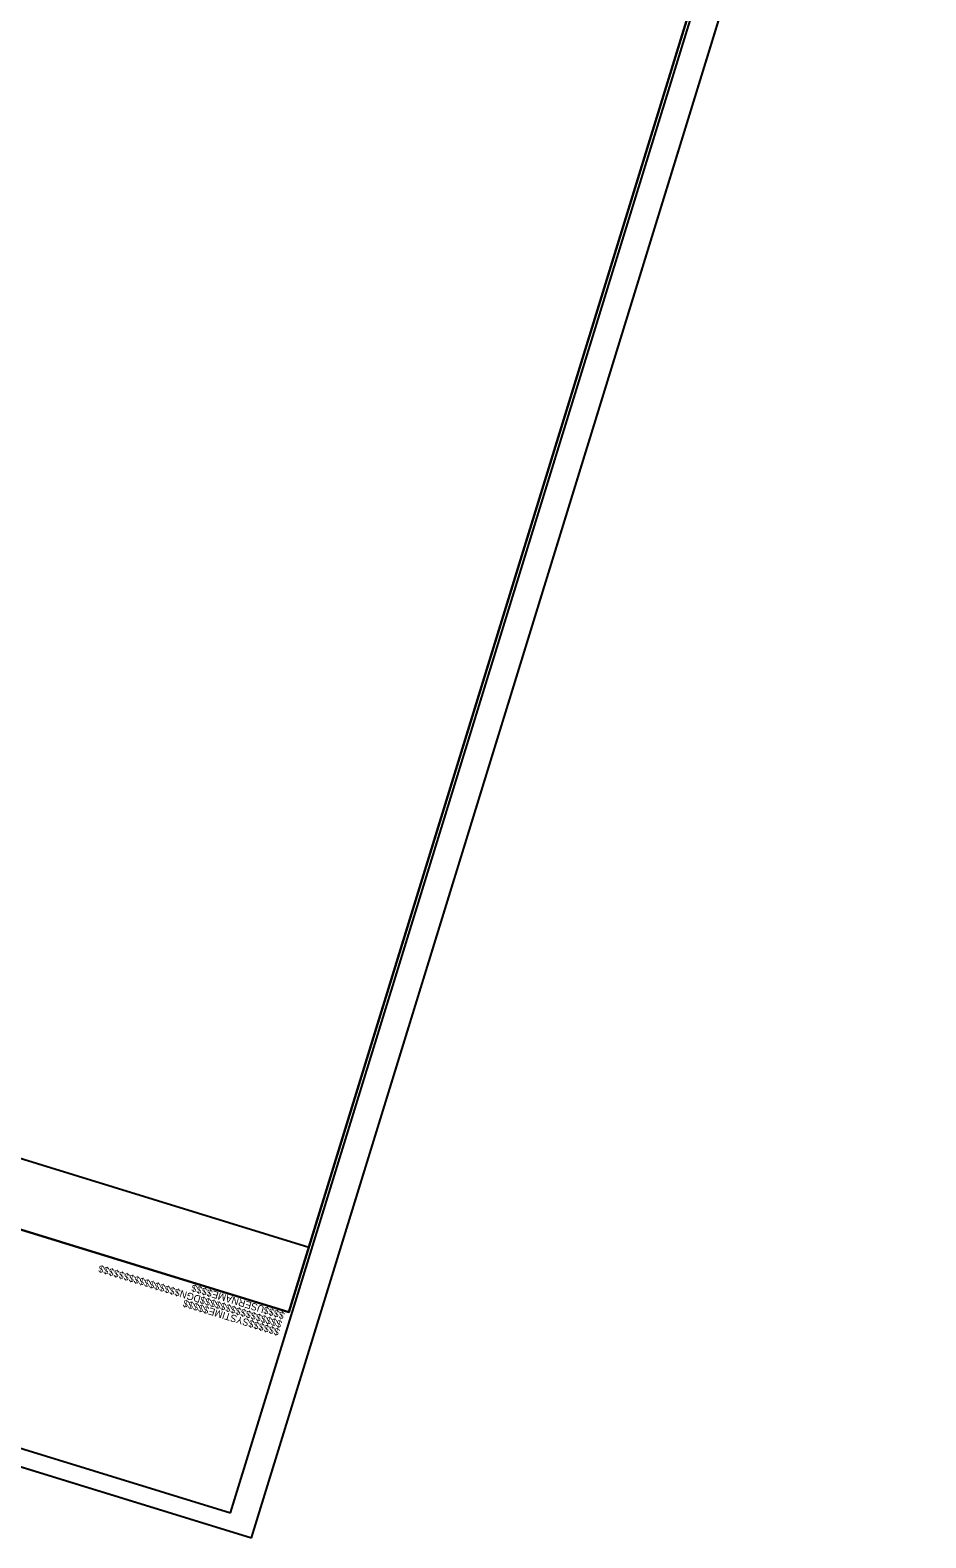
# Model space of a CAD drawing. Extents: x 1347957 to 1349499, y 1028289 to 1030503.
# Drawn here: x 1348841 to 1349499, y 1028289 to 1029396 of the extents above; entities that cross this region are included whole.
import ezdxf

# ---------------------------------------------------------------- set-up
doc = ezdxf.new("R2010")
doc.units = 0
for name, color, linetype in [('Sheet Clip Boundary CELL', 7, 'Continuous'), ('Sheet Cutting Line CELL', 7, 'Continuous'), ('Sheet Layout Plan Border', 7, 'Continuous'), ('Sheet Plan CELL', 7, 'Continuous'), ('Sheet Plan Layout CELL', 7, 'Continuous'), ('Sheet Plot Border Inside CELL', 7, 'Continuous'), ('Sheet Plot Border Outside CELL', 7, 'Continuous')]:
    doc.layers.add(name, color=color, linetype=linetype)

msp = doc.modelspace()

# ---------------------------------------------------------------- linework, layer by layer
at = {"layer": 'Sheet Clip Boundary CELL'}
msp.add_lwpolyline([(1349045.8, 1028502.3), (1349457.8, 1029840.3), (1348656.4, 1030087.1), (1348600.7, 1029906.2), (1348398.6, 1029968.5), (1348042.3, 1028811.4)], close=True, dxfattribs=at)
at = {"layer": 'Sheet Cutting Line CELL'}
for p, q in [((1349003.6, 1028288.8), (1349499, 1029897.7)), ((1347957.1, 1028611.1), (1349003.6, 1028288.8))]:
    msp.add_line(p, q, dxfattribs=at)
at = {"layer": 'Sheet Layout Plan Border'}
msp.add_lwpolyline([(1349045.8, 1028502.3), (1349457.8, 1029840.3), (1348656.4, 1030087.1), (1348600.7, 1029906.2), (1348398.6, 1029968.5), (1348042.3, 1028811.4)], close=True, dxfattribs=at)
at = {"layer": 'Sheet Plan CELL'}
msp.add_line((1349031, 1028454.5), (1349031, 1028454.5), dxfattribs=at)
for points in [[(1348469, 1030197.2), (1348027.5, 1028763.6), (1349031, 1028454.5), (1349472.5, 1029888.1)], [(1349031, 1028454.5), (1348027.6, 1028763.5), (1348410.1, 1030006), (1348553.6, 1029961.8), (1348612.4, 1030153), (1349472.5, 1029888.1)]]:
    msp.add_lwpolyline(points, close=True, dxfattribs=at)
at = {"layer": 'Sheet Plan Layout CELL'}
msp.add_lwpolyline([(1348027.6, 1028763.5), (1349031, 1028454.5), (1349472.5, 1029888.1), (1348671.1, 1030134.9), (1348600.7, 1029906.2), (1348398.6, 1029968.5)], close=True, dxfattribs=at)
at = {"layer": 'Sheet Plot Border Inside CELL'}
msp.add_lwpolyline([(1348988.3, 1028307.1), (1349478.6, 1029899.3), (1348470.3, 1030209.8), (1347980, 1028617.6)], close=True, dxfattribs=at)
at = {"layer": 'Sheet Plot Border Outside CELL'}
msp.add_lwpolyline([(1349003.6, 1028288.8), (1349499, 1029897.7), (1348452.5, 1030220), (1347957.1, 1028611.1)], close=True, dxfattribs=at)

# ---------------------------------------------------------------- texts
at = {"layer": 'Sheet Plan CELL'}
for s, p in [('$$$$$$$$$$$$$$$$DGN$$$$$$$$$$$$$$$$', (1349026.5, 1028447.9)), ('$$$$USERNAME$$$$', (1349028.4, 1028454.2)), ('$$$$$$SYSTIME$$$$$', (1349024.8, 1028442.1))]:
    msp.add_text(s, height=5.25, rotation=162.8834, dxfattribs=at).set_placement(p)

doc.saveas('drawing.dxf')
